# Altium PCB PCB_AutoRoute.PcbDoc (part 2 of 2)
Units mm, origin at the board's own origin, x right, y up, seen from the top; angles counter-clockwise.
Board outline 100 x 100 mm, 4 copper layers (Top Layer, AGND, PWR, Bottom Layer), stack 1.747 mm thick; 183 components, 95 nets, 503 pads, 230 vias.
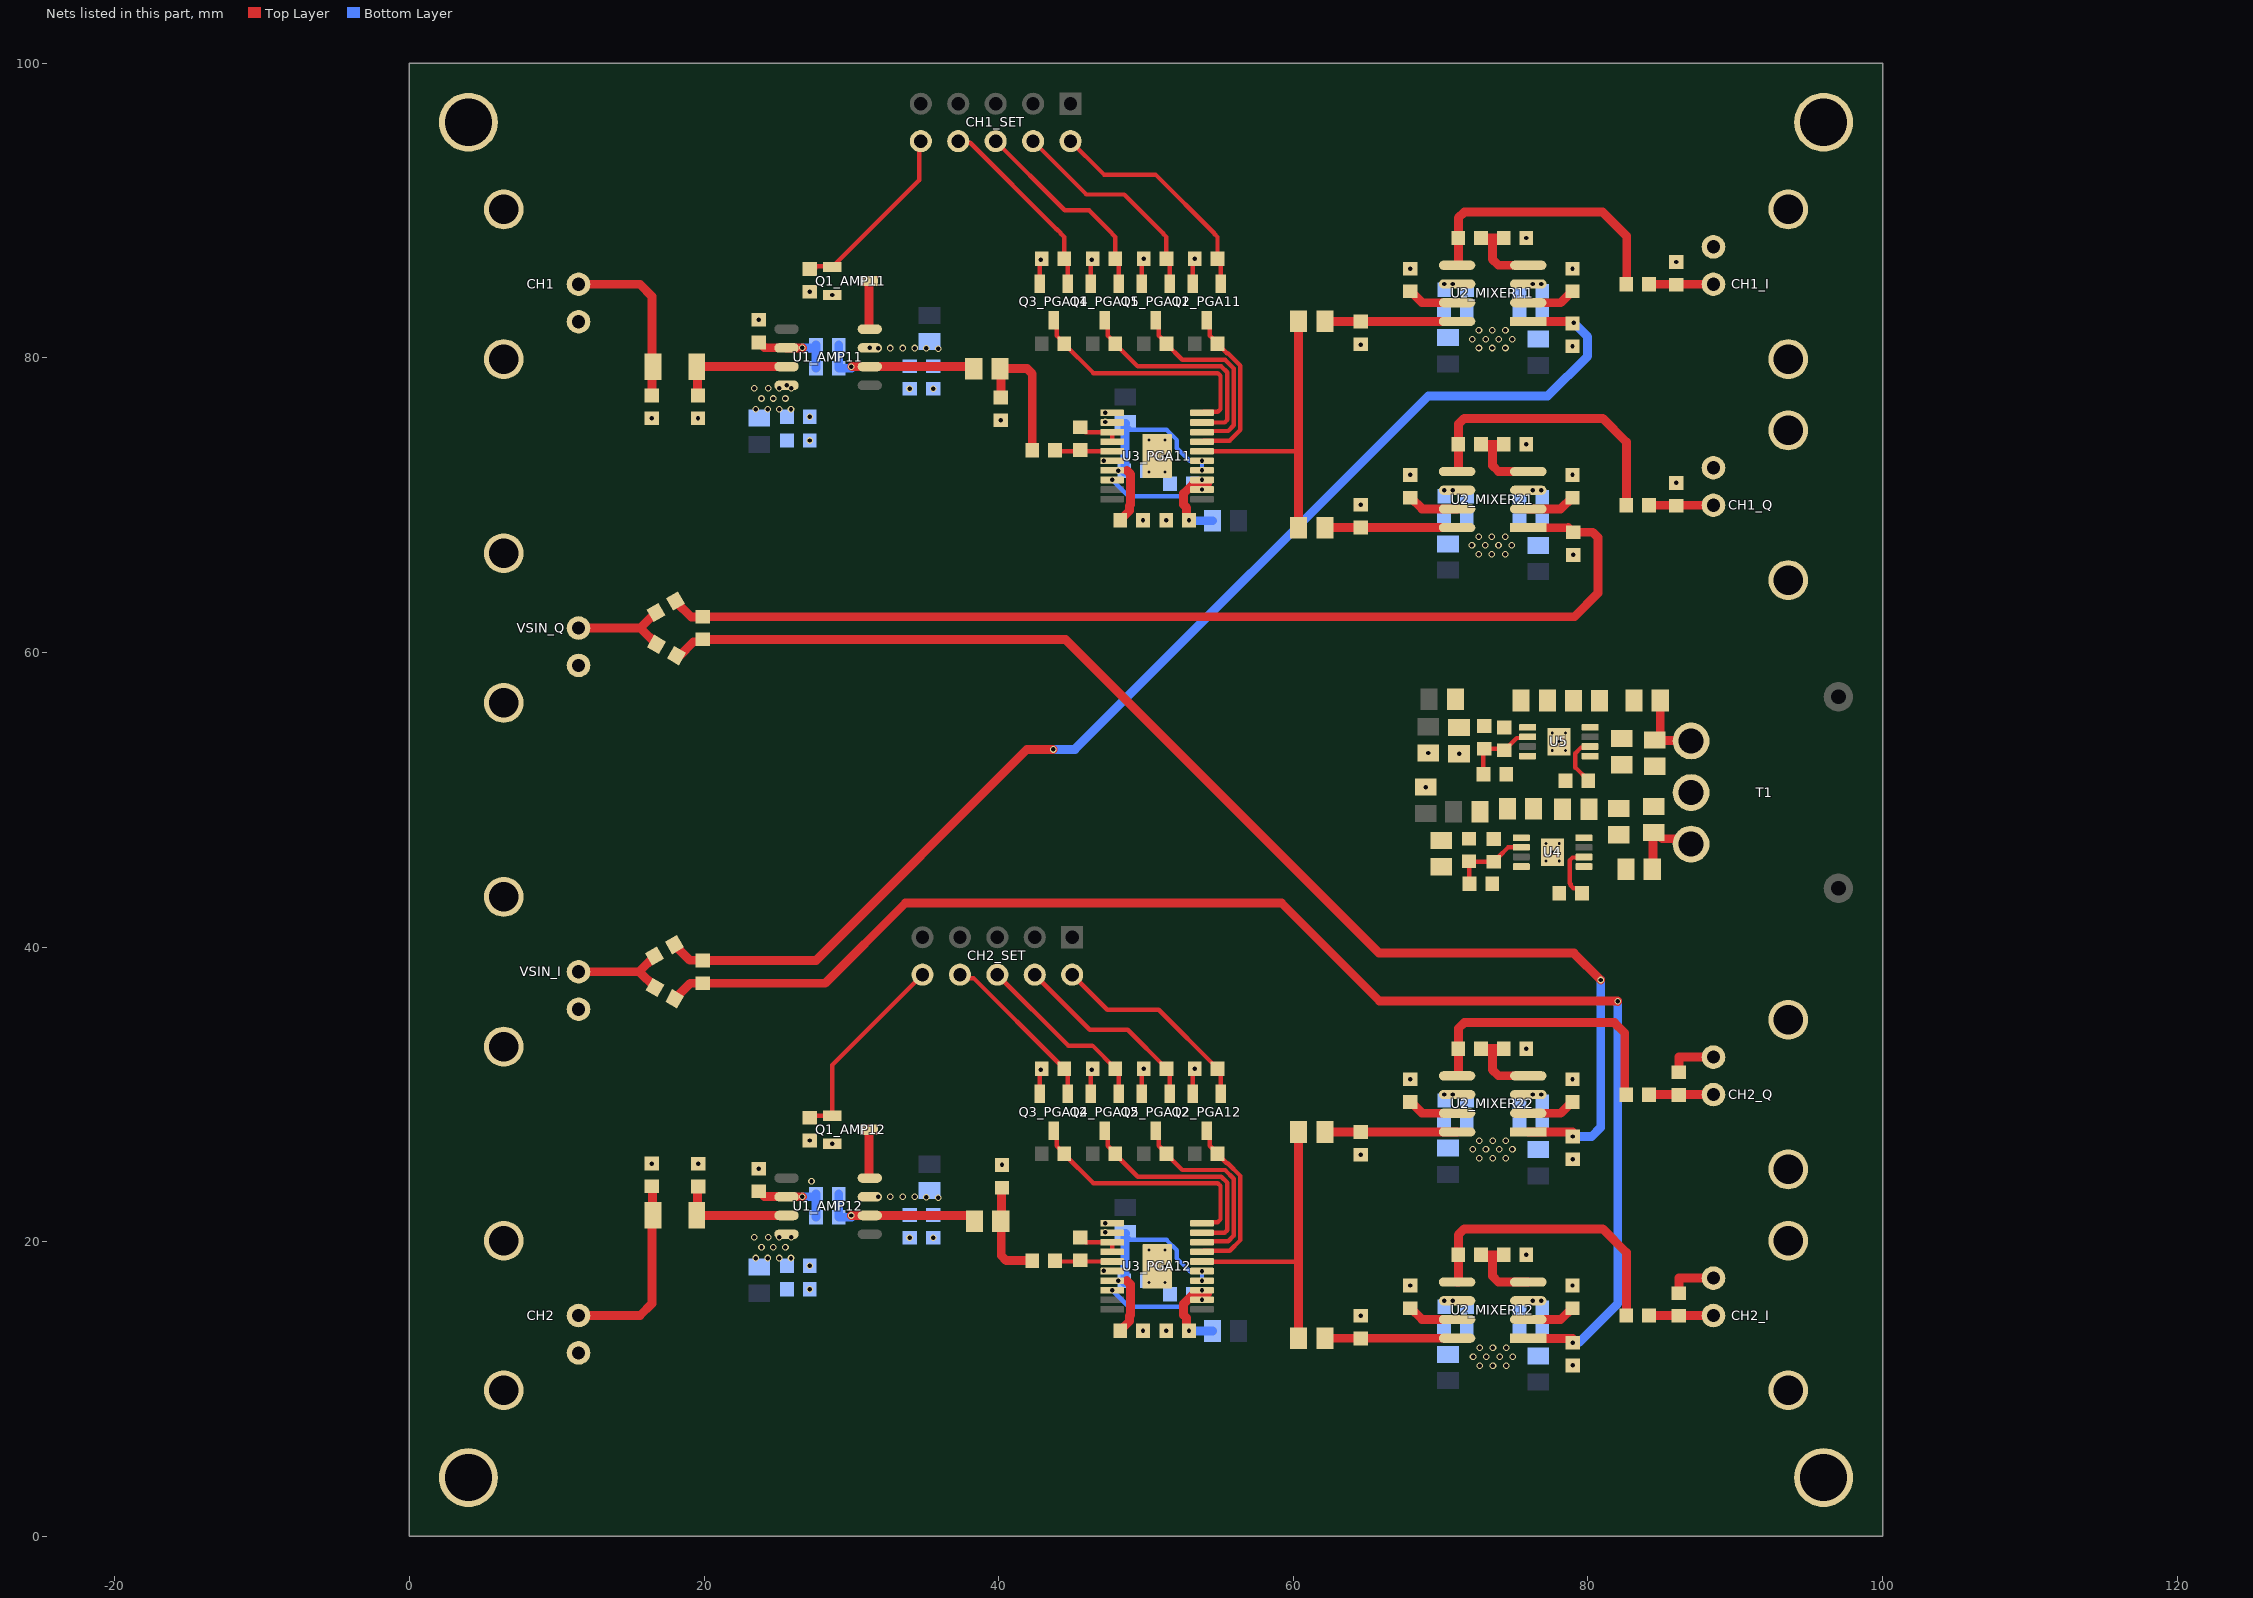
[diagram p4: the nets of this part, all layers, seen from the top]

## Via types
v1: diameter 0.45, hole 0.3, Top Layer to Bottom Layer, 208 vias
v2: diameter 0.5, hole 0.2, Top Layer to Bottom Layer, 12 vias
v3: diameter 0.5, hole 0.2, Top Layer to Bottom Layer, tented both sides, 10 vias

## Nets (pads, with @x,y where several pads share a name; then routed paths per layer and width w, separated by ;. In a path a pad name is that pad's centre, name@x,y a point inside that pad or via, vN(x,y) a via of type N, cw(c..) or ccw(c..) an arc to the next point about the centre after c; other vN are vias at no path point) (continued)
AGND: C2_CH1.1 C2_CH2.1 C3_CH1.1 C3_CH2.1 C4_AMP11.1 C4_AMP12.1 C5_AMP11.1 C5_AMP12.1 C6_AMP11.1 C6_AMP12.1 C7_AMP11.1 C7_AMP12.1 C9_MIXER11.1 C9_MIXER12.1 C9_MIXER21.1 C9_MIXER22.1 C10_MIXER11.1 C10_MIXER12.1 C10_MIXER21.1 C10_MIXER22.1 C11_MIXER11.1 C11_MIXER12.1 C11_MIXER21.1 C11_MIXER22.1 C12_MIXER11.1 C12_MIXER12.1 C12_MIXER21.1 C12_MIXER22.1 C13_PGA11.1 C13_PGA12.1 C14_PGA11.1 C14_PGA12.1 C15_PGA11.1 C15_PGA12.1 C16_PGA11.1 C16_PGA12.1 C19.1 C20.1 C21.1 C22.1 C24.1 C25.1 C26.1 C27.2 C28.2 C29.2 C30.2 C33.1 C34.1 C35.1 CH1.MH CH1_I.MH CH1_Q.MH CH2.MH CH2_I.MH CH2_Q.MH pad.MACH Q1_AMP11.2 Q1_AMP12.2 Q2_PGA11.2 Q2_PGA12.2 Q3_PGA11.2 Q3_PGA12.2 Q4_PGA11.2 Q4_PGA12.2 Q5_PGA11.2 Q5_PGA12.2 R3_AMP11.1 R3_AMP12.1 R5_AMP11.1 R5_AMP12.1 R7_MIXER11.1 R7_MIXER12.1 R7_MIXER21.1 R7_MIXER22.1 R11_PGA11.1 R11_PGA12.1 R13_PGA11.1 R13_PGA12.1 R15_PGA11.1 R15_PGA12.1 R17_PGA11.1 R17_PGA12.1 R20.1 R21.1 R23.1 R24.1 R28.1 R29.1 R30.1 R31.1 R33.1 R34.1 R41_MIXER11.1 R41_MIXER12.1 R41_MIXER21.1 R41_MIXER22.1 R42_MIXER11.1 R42_MIXER12.1 R42_MIXER21.1 R42_MIXER22.1 R43_CH1.1 R43_CH2.1 R44_CH1.1 R44_CH2.1 R45_CH1.1 R45_CH2.1 T1.2 U3_PGA11.1 U3_PGA11.2 U3_PGA11.6 U3_PGA11.21 U3_PGA12.1 U3_PGA12.2 U3_PGA12.6 U3_PGA12.21 U4.4 U4.9 U5.4 U5.9 VSIN_I.MH VSIN_Q.MH | length 20.7
  Top Layer w0.3: Q3_PGA12.2@42.782,30.048 42.782,31.611 R13_PGA12.1@42.914,31.743 ; Q3_PGA11.2@42.782,85.048 42.782,86.611 R13_PGA11.1@42.914,86.743 ; Q4_PGA12.2@46.249,30.048 46.249,31.611 R15_PGA12.1@46.381,31.743 ; Q4_PGA11.2@46.249,85.048 46.249,86.611 R15_PGA11.1@46.381,86.743 ; Q5_PGA12.2@49.715,30.048 49.715,31.611 v1(49.847,31.743) ; Q5_PGA11.2@49.715,85.048 49.715,86.611 v1(49.847,86.743) ; Q2_PGA12.2@53.182,30.048 53.182,31.611 v1(53.314,31.743) ; Q2_PGA11.2@53.182,85.048 53.182,86.611 v1(53.314,86.743)
  Top Layer w0.6: C2_CH2.1@86.175,16.515 86.175,17.54 CH2_I.MH@88.52,17.54 ; C3_CH2.1@86.175,31.515 86.175,32.54 CH2_Q.MH@88.52,32.54
  other v1: 72.65,11.6 73.55,11.6 74.45,11.6 78.975,11.61 72.2,12.2 73.1,12.2 74,12.2 74.9,12.2 72.65,12.8 73.55,12.8 74.45,12.8 49.795,13.975 51.38,13.975 64.575,14.98 27.17,16.775 67.95,17.04 78.95,17.04 47.125,18.025 27.17,18.375 75.82,19.12 33.95,20.28 35.55,20.28 47.225,20.65 47.225,21.275 27.295,24.125 23.725,24.97 40.225,25.22 19.6,25.295 16.45,25.315 78.975,25.61 72.625,25.675 73.525,25.675 74.425,25.675 64.575,25.915 72.175,26.275 73.075,26.275 73.975,26.275 74.875,26.275 28.7,26.65 72.625,26.875 73.525,26.875 74.425,26.875 27.175,26.88 67.95,31.04 78.95,31.04 42.848,31.677 46.315,31.677 75.82,33.12 69,50.865 71.25,53.135 69.15,53.185 79,66.63 72.575,66.675 73.475,66.675 74.375,66.675 72.125,67.275 73.025,67.275 73.925,67.275 74.825,67.275 72.575,67.875 73.475,67.875 74.375,67.875 49.795,68.975 51.38,68.975 64.575,70.025 86,71.515 67.95,72.06 78.95,72.06 47.125,73.025 75.82,74.14 27.17,74.397 47.225,75.65 40.15,75.78 16.46,75.905 19.59,75.905 27.17,75.997 47.225,76.275 33.95,77.902 35.55,77.902 72.6,80.675 73.5,80.675 74.4,80.675 78.95,80.8 64.575,80.9 72.15,81.275 73.05,81.275 73.95,81.275 74.85,81.275 72.6,81.875 73.5,81.875 74.4,81.875 23.725,82.592 28.7,84.272 27.175,84.502 67.95,86.06 78.95,86.06 86,86.515 42.848,86.677 46.315,86.677 75.82,88.14
  other v2: 50.202,17.243 51.302,17.243 50.202,18.343 51.302,18.343 50.202,19.443 51.302,19.443 50.202,72.243 51.302,72.243 50.202,73.343 51.302,73.343 50.202,74.443 51.302,74.443
  other v3: 77.15,45.85 78.05,45.85 77.6,46.45 77.15,47.05 78.05,47.05 77.575,53.35 78.475,53.35 78.025,53.95 77.575,54.55 78.475,54.55
AVDD_AMP11: C4_AMP11.2 C5_AMP11.2 FB1_AMP11.2 U1_AMP11.7
  other v1: 35.9,80.622 35.075,80.647 31.825,80.672 32.65,80.672 33.5,80.672 34.3,80.672 31.25,80.682
AVDD_AMP12: C4_AMP12.2 C5_AMP12.2 FB1_AMP12.2 U1_AMP12.7
  other v1: 35.9,23 35.075,23.025 31.825,23.05 32.65,23.05 33.5,23.05 34.3,23.05
AVDD_MIXER11: C9_MIXER11.2 C10_MIXER11.2 FB3_MIXER11.2 U2_MIXER11.6
  other v1: 70.243,85.02 70.818,85.02
AVDD_MIXER12: C9_MIXER12.2 C10_MIXER12.2 FB3_MIXER12.2 U2_MIXER12.6
  other v1: 70.243,16 70.818,16
AVDD_MIXER21: C9_MIXER21.2 C10_MIXER21.2 FB3_MIXER21.2 U2_MIXER21.6
  other v1: 70.243,71.02 70.818,71.02
AVDD_MIXER22: C9_MIXER22.2 C10_MIXER22.2 FB3_MIXER22.2 U2_MIXER22.6
  other v1: 70.243,30 70.818,30
AVDD_PGA11: C13_PGA11.2 C14_PGA11.2 FB5_PGA11.2 U3_PGA11.8 U3_PGA11.12 U3_PGA11.13 | length 12.2
  Top Layer w0.6: v1(52.92,68.975) 52.755,69.14 52.755,69.829 52.55,70.035 52.55,70.801 53.223,71.475 54.175,71.475
  Bottom Layer w0.3: v1(47.702,71.718) 48.82,70.6 52.55,70.6 53.018,71.068 v1(53.802,71.068)
  Bottom Layer w0.6: v1(52.92,68.975) 52.945,68.95 FB5_PGA11.2@54.51,68.95
  other v1: 53.802,71.718
AVDD_PGA12: C13_PGA12.2 C14_PGA12.2 FB5_PGA12.2 U3_PGA12.8 U3_PGA12.12 U3_PGA12.13 | length 12.2
  Top Layer w0.6: v1(52.92,13.975) 52.755,14.14 52.755,14.829 52.55,15.035 52.55,15.801 53.223,16.475 54.175,16.475
  Bottom Layer w0.3: v1(47.702,16.718) 48.82,15.6 52.55,15.6 53.018,16.068 v1(53.802,16.068)
  Bottom Layer w0.6: v1(52.92,13.975) 52.945,13.95 FB5_PGA12.2@54.51,13.95
  other v1: 53.802,16.718
AVEE_AMP11: C6_AMP11.2 C7_AMP11.2 FB2_AMP11.2 U1_AMP11.4
  other v1: 23.5,76.522 24.325,76.522 25.1,76.522 25.9,76.522 23.9,77.247 24.7,77.247 25.525,77.247 23.4,77.947 24.35,77.947 25.1,77.947 25.925,77.947 25.6,78.142
AVEE_AMP12: C6_AMP12.2 C7_AMP12.2 FB2_AMP12.2 U1_AMP12.4
  other v1: 23.5,18.9 24.325,18.9 25.1,18.9 25.9,18.9 23.9,19.625 24.7,19.625 25.525,19.625 23.4,20.325 24.35,20.325 25.1,20.325 25.925,20.325
AVEE_MIXER11: C11_MIXER11.2 C12_MIXER11.2 FB4_MIXER11.2 U2_MIXER11.3
  other v1: 76.25,85.02 76.825,85.02
AVEE_MIXER12: C11_MIXER12.2 C12_MIXER12.2 FB4_MIXER12.2 U2_MIXER12.3
  other v1: 76.25,16 76.825,16
AVEE_MIXER21: C11_MIXER21.2 C12_MIXER21.2 FB4_MIXER21.2 U2_MIXER21.3
  other v1: 76.25,71.02 76.825,71.02
AVEE_MIXER22: C11_MIXER22.2 C12_MIXER22.2 FB4_MIXER22.2 U2_MIXER22.3
  other v1: 76.25,30 76.825,30
AVEE_PGA11: C15_PGA11.2 C16_PGA11.2 FB6_PGA11.2 U3_PGA11.7 U3_PGA11.14 U3_PGA11.15 | length 14.4
  Top Layer w0.6: C15_PGA11.2@48.255,68.975 48.255,69 48.878,69.623 48.878,69.958 48.954,70.035 48.954,72.101 48.688,72.368
  Bottom Layer w0.3: FB6_PGA11.2@48.565,75.525 48.96,75.13 51.396,75.13 52.1,74.426 52.1,73.875 52.957,73.018 v1(53.802,73.018) v1(53.802,72.368)
  Bottom Layer w0.6: C16_PGA11.2@48.53,72.25 48.565,72.285 48.565,75.525 FB6_PGA11.2@48.6,75.56
  other v1: 48.125,72.35
AVEE_PGA12: C15_PGA12.2 C16_PGA12.2 FB6_PGA12.2 U3_PGA12.7 U3_PGA12.14 U3_PGA12.15 | length 14.4
  Top Layer w0.6: C15_PGA12.2@48.255,13.975 48.255,14 48.878,14.623 48.878,14.958 48.954,15.035 48.954,17.101 48.688,17.368
  Bottom Layer w0.3: FB6_PGA12.2@48.565,20.525 48.96,20.13 51.396,20.13 52.1,19.426 52.1,18.875 52.957,18.018 v1(53.802,18.018) v1(53.802,17.368)
  Bottom Layer w0.6: C16_PGA12.2@48.53,17.25 48.565,17.285 48.565,20.525 FB6_PGA12.2@48.6,20.56
  other v1: 48.125,17.35
CH1_CONT_BIT0: CH1_SET.10 Q1_AMP11.1 R5_AMP11.2 | length 12.9
  Top Layer w0.3: R5_AMP11.2@27.562,86.042 27.351,86.042 27.175,86.217 Q1_AMP11.1@28.472,86.217 ; Q1_AMP11.1@28.7,86.172 34.602,92.074 CH1_SET.10@34.602,94.83
CH1_CONT_BIT1: CH1_SET.2 Q2_PGA11.1 R11_PGA11.2 | length 16.1
  Top Layer w0.3: CH1_SET.2@44.762,94.83 47.147,92.445 50.644,92.445 54.626,88.463 54.626,88.438 54.854,88.21 R11_PGA11.2@54.854,86.743 55.082,86.515 Q2_PGA11.1@55.082,85.048
CH1_CONT_BIT2: CH1_SET.8 Q3_PGA11.1 R13_PGA11.2 | length 13.3
  Top Layer w0.3: CH1_SET.8@37.142,94.83 37.372,94.6 38.064,94.6 43.886,88.778 43.911,88.778 44.226,88.463 44.226,88.438 44.454,88.21 R13_PGA11.2@44.454,86.743 44.682,86.515 Q3_PGA11.1@44.682,85.048
CH1_CONT_BIT3: CH1_SET.6 Q4_PGA11.1 R15_PGA11.2 | length 14.3
  Top Layer w0.3: CH1_SET.6@39.682,94.83 44.492,90.02 46.136,90.02 47.693,88.463 47.693,88.438 47.921,88.21 R15_PGA11.2@47.921,86.743 48.149,86.515 Q4_PGA11.1@48.149,85.048
CH1_CONT_BIT4: CH1_SET.4 Q5_PGA11.1 R17_PGA11.2 | length 15.2
  Top Layer w0.3: CH1_SET.4@42.222,94.83 45.957,91.095 48.527,91.095 51.159,88.463 51.159,88.438 51.387,88.21 R17_PGA11.2@51.387,86.743 51.615,86.515 Q5_PGA11.1@51.615,85.048
CH2_CONT_BIT0: CH2_SET.10 Q1_AMP12.1 R5_AMP12.2 | length 13.7
  Top Layer w0.3: R5_AMP12.2@27.175,28.42 27.305,28.55 Q1_AMP12.1@28.7,28.55 28.7,32.005 CH2_SET.10@34.83,38.135
CH2_CONT_BIT1: CH2_SET.2 Q2_PGA12.1 R11_PGA12.2 | length 14.3
  Top Layer w0.3: CH2_SET.2@44.99,38.135 47.375,35.75 50.872,35.75 R11_PGA12.2@54.854,31.768 ; R11_PGA12.2@54.854,31.743 55.082,31.515 Q2_PGA12.1@55.082,30.048
CH2_CONT_BIT2: CH2_SET.8 Q3_PGA12.1 R13_PGA12.2 | length 11
  Top Layer w0.3: CH2_SET.8@37.37,38.135 37.6,37.905 38.292,37.905 R13_PGA12.2@44.114,32.083 ; R13_PGA12.2@44.454,31.743 44.682,31.515 Q3_PGA12.1@44.682,30.048
CH2_CONT_BIT3: CH2_SET.6 Q4_PGA12.1 R15_PGA12.2 | length 12.4
  Top Layer w0.3: CH2_SET.6@39.91,38.135 44.72,33.325 46.364,33.325 R15_PGA12.2@47.921,31.768 ; R15_PGA12.2@47.921,31.743 48.149,31.515 Q4_PGA12.1@48.149,30.048
CH2_CONT_BIT4: CH2_SET.4 Q5_PGA12.1 R17_PGA12.2 | length 13.4
  Top Layer w0.3: CH2_SET.4@42.45,38.135 46.185,34.4 48.755,34.4 R17_PGA12.2@51.387,31.768 ; R17_PGA12.2@51.387,31.743 51.615,31.515 Q5_PGA12.1@51.615,30.048
NetC1_CH1_1: C1_CH1.1 C8_AMP11.2 R4_AMP11.2 U1_AMP11.6 | length 11
  Top Layer w0.6: v1@30.025,79.412 U1_AMP11.6@31.25,79.412 38.31,79.412 C1_CH1.1@38.31,79.275
  Bottom Layer w0.6: C8_AMP11.2@29.145,80.872 R4_AMP11.2@29.145,79.297 30.025,79.297 v1@30.025,79.412
  other v1: 30,79.412
NetC1_CH1_2: C1_CH1.2 R8_PGA11.1 R43_CH1.2 | length 9.6
  Top Layer w0.6: R43_CH1.2@40.15,77.32 40.15,79.275 C1_CH1.2@40.09,79.275 41.931,79.275 42.282,78.924 R8_PGA11.1@42.282,73.723
NetC1_CH2_1: C1_CH2.1 C8_AMP12.2 R4_AMP12.2 U1_AMP12.6 | length 11.2
  Top Layer w0.6: v1(30,21.79) 38.08,21.79 38.36,21.51 C1_CH2.1@38.36,21.4
  Bottom Layer w0.6: C8_AMP12.2@29.145,23.25 R4_AMP12.2@29.145,21.675 30.025,21.675 v1@30.025,21.79
NetC1_CH2_2: C1_CH2.2 R8_PGA12.1 R43_CH2.2 | length 7.2
  Top Layer w0.6: C1_CH2.2@40.14,21.4 C1_CH2.2@40.175,21.435 ; R43_CH2.2@40.225,23.68 40.183,23.637 C1_CH2.2@40.183,21.75 ; R8_PGA12.1@42.282,18.723 40.526,18.723 40.175,19.074 C1_CH2.2@40.175,21.435 ; C1_CH2.2@40.175,21.435 40.175,21.742 C1_CH2.2@40.183,21.75 ; C1_CH2.2@40.175,21.435 40.183,21.442 C1_CH2.2@40.183,21.75
NetC2_CH1_2: C2_CH1.2 CH1_I.1 R1_CH1.1 | length 4.3
  Top Layer w0.6: R1_CH1.1@84.17,85 CH1_I.1@88.52,85
NetC2_CH2_2: C2_CH2.2 CH2_I.1 R1_CH2.1 | length 4.4
  Top Layer w0.6: R1_CH2.1@84.145,15 CH2_I.1@88.52,15
NetC3_CH1_2: C3_CH1.2 CH1_Q.1 R2_CH1.1 | length 4.3
  Top Layer w0.6: R2_CH1.1@84.17,70 CH1_Q.1@88.52,70
NetC3_CH2_2: C3_CH2.2 CH2_Q.1 R2_CH2.1 | length 4.4
  Top Layer w0.6: R2_CH2.1@84.145,30 CH2_Q.1@88.52,30
NetC8_AMP11_1: C8_AMP11.1 R3_AMP11.2 R4_AMP11.1 U1_AMP11.2 | length 5.7
  Top Layer w0.6: R3_AMP11.2@23.725,81.052 23.75,81.052 24.11,80.691 25.59,80.691 U1_AMP11.2@25.6,80.682 v1(26.675,80.682)
  Bottom Layer w0.6: v1(26.675,80.682) 27.44,80.682 C8_AMP11.1@27.605,80.847 ; R4_AMP11.1@27.605,79.297 C8_AMP11.1@27.605,80.847 ; C8_AMP11.1@27.605,80.872 C8_AMP11.1@27.605,80.847
NetC8_AMP12_1: C8_AMP12.1 R3_AMP12.2 R4_AMP12.1 U1_AMP12.2 | length 5.7
  Top Layer w0.6: R3_AMP12.2@23.725,23.43 23.75,23.43 24.11,23.07 25.59,23.07 U1_AMP12.2@25.6,23.06 v1(26.675,23.06)
  Bottom Layer w0.6: v1(26.675,23.06) 27.44,23.06 C8_AMP12.1@27.605,23.225 ; R4_AMP12.1@27.605,21.675 C8_AMP12.1@27.605,23.225 ; C8_AMP12.1@27.605,23.25 C8_AMP12.1@27.605,23.225
NetC17_1: C17.1 CH1.1 R20.2 | length 12.1
  Top Layer w0.6: CH1.1@11.48,85 15.65,85 16.46,84.19 R20.2@16.46,77.445
NetC17_2: C17.2 R21.2 U1_AMP11.3 | length 8.1
  Top Layer w0.6: R21.2@19.59,77.445 19.552,77.483 19.552,79.374 C17.2@19.515,79.412 U1_AMP11.3@25.6,79.412
NetC18_1: C18.1 CH2.1 R30.2 | length 14.1
  Top Layer w0.6: CH2.1@11.48,15 15.65,15 16.46,15.81 C18.1@16.46,22.555 ; R30.2@16.45,23.775 16.492,23.733 16.492,21.833 C18.1@16.535,21.79
NetC18_2: C18.2 R31.2 U1_AMP12.3 | length 8.1
  Top Layer w0.6: R31.2@19.6,23.755 19.557,23.712 19.557,21.833 C18.2@19.515,21.79 U1_AMP12.3@25.6,21.79
NetC19_2: C19.2 FB7.2 T1.1 | length 5.4
  Top Layer w0.6: FB7.2@84.365,45.3 84.42,45.355 84.42,47.73 C19.2@84.475,47.785 84.63,47.785 85.051,47.364 86.636,47.364 T1.1@87,47
NetC21_2: C21.2 C23.2 C25.2 FB8.2 R32.2 U4.1
NetC23_1: C23.1 R32.1 R33.2 U4.2 | length 5.5
  Top Layer w0.3: C23.1@71.925,45.83 C23.1@71.95,45.805 ; R33.2@71.955,44.3 71.955,45.8 C23.1@71.95,45.805 ; U4.2@75.475,46.775 74.57,46.775 73.94,46.145 73.94,46.12 73.625,45.805 C23.1@71.95,45.805
NetC26_2: C26.2 U4.6 | length 3.8
  Top Layer w0.3: C26.2@79.595,43.675 79.595,43.7 79.28,44.015 78.998,44.015 78.822,44.191 78.822,44.29 78.775,44.338 78.775,45.916 78.951,46.092 79.692,46.092 U4.6@79.725,46.125
NetC27_1: C27.1 FB9.1 T1.3 | length 5.3
  Top Layer w0.6: C27.1@84.525,54.065 84.557,54.033 C27.1@84.592,54.033 ; FB9.1@84.905,56.75 84.905,54.345 C27.1@84.592,54.033 ; T1.3@87,54 86.967,54.033 C27.1@84.592,54.033
NetC28_1: C28.1 C34.2 FB9.2 U5.5 U5.8
NetC29_1: C29.1 C35.2 C36.2 FB10.2 R35.2 U5.1
NetC31_CH1_1: C31_CH1.1 C32_CH1.1 U3_PGA11.16 | length 20.5
  Top Layer w0.3: U3_PGA11.16@53.802,73.668 60.253,73.668
  Top Layer w0.6: C32_CH1.1@60.36,68.48 60.36,73.775 C31_CH1.1@60.36,82.48
NetC31_CH1_2: C31_CH1.2 R44_CH1.2 U2_MIXER11.8 | length 9
  Top Layer w0.6: C31_CH1.2@62.14,82.48 U2_MIXER11.8@71.118,82.48
NetC31_CH2_1: C31_CH2.1 C32_CH2.1 U3_PGA12.16 | length 20.5
  Top Layer w0.3: U3_PGA12.16@53.802,18.648 60.253,18.648
  Top Layer w0.6: C31_CH2.1@60.36,13.46 60.36,18.755 C32_CH2.1@60.36,27.46
NetC31_CH2_2: C31_CH2.2 R44_CH2.2 U2_MIXER12.8 | length 9
  Top Layer w0.6: C31_CH2.2@62.14,13.46 U2_MIXER12.8@71.118,13.46
NetC32_CH1_2: C32_CH1.2 R45_CH1.2 U2_MIXER21.8 | length 9
  Top Layer w0.6: C32_CH1.2@62.14,68.48 U2_MIXER21.8@71.118,68.48
NetC32_CH2_2: C32_CH2.2 R45_CH2.2 U2_MIXER22.8 | length 9
  Top Layer w0.6: C32_CH2.2@62.14,27.46 U2_MIXER22.8@71.118,27.46
NetC33_2: C33.2 U5.6 | length 3.4
  Top Layer w0.3: C33.2@80.02,51.3 80.02,51.325 79.15,52.195 79.15,53.174 79.526,53.55 80.075,53.55 U5.6@80.15,53.625
NetC36_1: C36.1 R34.2 R35.1 U5.2 | length 5.1
  Top Layer w0.3: R34.2@72.905,51.75 72.905,53.41 C36.1@72.975,53.48 74.25,53.48 R35.1@74.35,53.38 ; R35.1@74.325,53.38 R35.1@74.35,53.38 ; U5.2@75.9,54.275 75.825,54.2 75.17,54.2 R35.1@74.35,53.38
NetQ1_AMP11_3: Q1_AMP11.3 U1_AMP11.8 | length 3.3
  Top Layer w0.6: Q1_AMP11.3@31.2,85.222 31.2,81.975 31.223,81.952 U1_AMP11.8@31.25,81.952
NetQ1_AMP12_3: Q1_AMP12.3 U1_AMP12.8 | length 3.3
  Top Layer w0.6: Q1_AMP12.3@31.2,27.6 31.2,24.353 31.223,24.33 U1_AMP12.8@31.25,24.33
NetQ2_PGA11_3: Q2_PGA11.3 R10_PGA11.1 U3_PGA11.17 | length 11.4
  Top Layer w0.3: U3_PGA11.17@53.802,74.318 53.877,74.393 55.677,74.393 56.412,75.128 56.412,79.472 55.556,80.328 55.474,80.328 54.854,80.948 54.854,80.998 54.332,81.52 54.332,82.348 Q2_PGA11.3@54.132,82.548
NetQ2_PGA12_3: Q2_PGA12.3 R10_PGA12.1 U3_PGA12.17 | length 11.4
  Top Layer w0.3: U3_PGA12.17@53.802,19.318 53.877,19.393 55.677,19.393 56.412,20.128 56.412,24.472 55.556,25.328 55.474,25.328 54.854,25.948 54.854,25.998 54.332,26.52 54.332,27.348 Q2_PGA12.3@54.132,27.548
NetQ3_PGA11_3: Q3_PGA11.3 R12_PGA11.1 U3_PGA11.20 | length 17
  Top Layer w0.3: Q3_PGA11.3@43.732,82.548 43.932,82.348 43.932,81.52 44.454,80.998 R12_PGA11.1@44.454,80.973 44.454,80.948 46.431,78.971 54.879,78.971 55.055,78.795 55.055,76.523 54.875,76.343 53.877,76.343 U3_PGA11.20@53.802,76.268
NetQ3_PGA12_3: Q3_PGA12.3 R12_PGA12.1 U3_PGA12.20 | length 17
  Top Layer w0.3: Q3_PGA12.3@43.732,27.548 43.932,27.348 43.932,26.52 44.454,25.998 R12_PGA12.1@44.454,25.973 44.454,25.948 46.431,23.971 54.879,23.971 55.055,23.795 55.055,21.523 54.875,21.343 53.877,21.343 U3_PGA12.20@53.802,21.268
NetQ4_PGA11_3: Q4_PGA11.3 R14_PGA11.1 U3_PGA11.19 | length 15.3
  Top Layer w0.3: Q4_PGA11.3@47.199,82.548 47.399,82.348 47.399,81.52 47.921,80.998 R14_PGA11.1@47.921,80.973 ; R14_PGA11.1@47.921,80.948 49.446,79.423 55.107,79.423 55.507,79.023 55.507,75.794 55.331,75.618 U3_PGA11.19@53.802,75.618
NetQ4_PGA12_3: Q4_PGA12.3 R14_PGA12.1 U3_PGA12.19 | length 15.3
  Top Layer w0.3: Q4_PGA12.3@47.199,27.548 47.399,27.348 47.399,26.52 47.921,25.998 R14_PGA12.1@47.921,25.973 ; R14_PGA12.1@47.921,25.948 49.446,24.423 55.107,24.423 55.507,24.023 55.507,20.794 55.331,20.618 U3_PGA12.19@53.802,20.618
NetQ5_PGA11_3: Q5_PGA11.3 R16_PGA11.1 U3_PGA11.18 | length 13.4
  Top Layer w0.3: Q5_PGA11.3@50.665,82.548 50.865,82.348 50.865,81.52 51.387,80.998 51.387,80.948 52.46,79.875 55.369,79.875 55.959,79.285 55.959,75.425 55.577,75.043 53.877,75.043 U3_PGA11.18@53.802,74.968
NetQ5_PGA12_3: Q5_PGA12.3 R16_PGA12.1 U3_PGA12.18 | length 13.4
  Top Layer w0.3: Q5_PGA12.3@50.665,27.548 50.865,27.348 50.865,26.52 51.387,25.998 51.387,25.948 52.46,24.875 55.369,24.875 55.959,24.285 55.959,20.425 55.577,20.043 53.877,20.043 U3_PGA12.18@53.802,19.968
NetR1_CH1_2: R1_CH1.2 R6_MIXER11.2 U2_MIXER11.5 | length 18.8
  Top Layer w0.6: U2_MIXER11.5@71.118,86.29 71.195,86.29 71.205,86.3 R6_MIXER11.2@71.205,88.14 71.205,89.505 71.6,89.9 81,89.9 82.63,88.27 R1_CH1.2@82.63,85
NetR1_CH2_2: R1_CH2.2 R6_MIXER12.2 U2_MIXER12.5 | length 19.8
  Top Layer w0.6: U2_MIXER12.5@71.118,17.27 71.195,17.27 71.205,17.28 R6_MIXER12.2@71.205,19.12 71.205,20.485 71.6,20.88 81,20.88 82.605,19.275 R1_CH2.2@82.605,15
NetR2_CH1_2: R2_CH1.2 R6_MIXER21.2 U2_MIXER21.5 | length 19.8
  Top Layer w0.6: U2_MIXER21.5@71.118,72.29 71.195,72.29 71.205,72.3 R6_MIXER21.2@71.205,74.14 71.205,75.505 71.6,75.9 81,75.9 82.605,74.295 R2_CH1.2@82.605,70
NetR2_CH2_2: R2_CH2.2 R6_MIXER22.2 U2_MIXER22.5 | length 19.3
  Top Layer w0.6: U2_MIXER22.5@71.118,31.27 71.195,31.27 71.205,31.28 R6_MIXER22.2@71.205,33.12 71.205,34.485 71.6,34.88 81.795,34.88 82.5,34.175 82.5,30.105 R2_CH2.2@82.605,30
NetR8_PGA11_2: R8_PGA11.2 R9_PGA11.1 U3_PGA11.5 | length 3.9
  Top Layer w0.3: R8_PGA11.2@43.822,73.723 43.877,73.668 U3_PGA11.5@47.702,73.668
NetR8_PGA12_2: R8_PGA12.2 R9_PGA12.1 U3_PGA12.5 | length 3.9
  Top Layer w0.3: R8_PGA12.2@43.822,18.723 43.877,18.668 U3_PGA12.5@47.702,18.668
NetR18_2: R18.2 R22.2 VSIN_Q.1 | length 7.3
  Top Layer w0.6: VSIN_Q.1@11.48,61.667 15.677,61.667 ; R18.2@16.741,62.73 15.678,61.667 15.677,61.667 ; R22.2@16.783,60.56 15.677,61.667
NetR25_2: R25.2 R27.2 VSIN_I.1 | length 7.1
  Top Layer w0.6: VSIN_I.1@11.48,38.333 15.583,38.333 ; R25.2@16.65,39.4 15.583,38.333 ; R27.2@16.675,37.27 15.612,38.333 15.583,38.333
NetR41_MIXER11_2: R41_MIXER11.2 U2_MIXER11.7 | length 3.5
  Top Layer w0.6: R41_MIXER11.2@67.95,84.52 67.975,84.52 68.745,83.75 U2_MIXER11.7@71.118,83.75
NetR41_MIXER12_2: R41_MIXER12.2 U2_MIXER12.7 | length 3.5
  Top Layer w0.6: R41_MIXER12.2@67.95,15.5 67.975,15.5 68.745,14.73 U2_MIXER12.7@71.118,14.73
NetR41_MIXER21_2: R41_MIXER21.2 U2_MIXER21.7 | length 3.5
  Top Layer w0.6: R41_MIXER21.2@67.95,70.52 67.975,70.52 68.745,69.75 U2_MIXER21.7@71.118,69.75
NetR41_MIXER22_2: R41_MIXER22.2 U2_MIXER22.7 | length 3.5
  Top Layer w0.6: R41_MIXER22.2@67.95,29.5 67.975,29.5 68.745,28.73 U2_MIXER22.7@71.118,28.73
NetR42_MIXER11_2: R42_MIXER11.2 U2_MIXER11.2 | length 3.3
  Top Layer w0.6: U2_MIXER11.2@75.95,83.75 78.155,83.75 78.925,84.52 R42_MIXER11.2@78.95,84.52
NetR42_MIXER12_2: R42_MIXER12.2 U2_MIXER12.2 | length 3.3
  Top Layer w0.6: U2_MIXER12.2@75.95,14.73 78.155,14.73 78.925,15.5 R42_MIXER12.2@78.95,15.5
NetR42_MIXER21_2: R42_MIXER21.2 U2_MIXER21.2 | length 3.3
  Top Layer w0.6: U2_MIXER21.2@75.95,69.75 78.155,69.75 78.925,70.52 R42_MIXER21.2@78.95,70.52
NetR42_MIXER22_2: R42_MIXER22.2 U2_MIXER22.2 | length 3.3
  Top Layer w0.6: U2_MIXER22.2@75.95,28.73 78.155,28.73 78.925,29.5 R42_MIXER22.2@78.95,29.5
VDD_13P0V: C20.2 C24.2 FB7.1 U4.5 U4.8
VINPGA-_PGA11: R9_PGA11.2 U3_PGA11.3 U3_PGA11.4 | length 3
  Top Layer w0.3: R9_PGA11.2@45.527,75.293 45.552,75.293 45.877,74.968 U3_PGA11.3@47.702,74.968 U3_PGA11.4@47.702,74.318
VINPGA-_PGA12: R9_PGA12.2 U3_PGA12.3 U3_PGA12.4 | length 3
  Top Layer w0.3: R9_PGA12.2@45.527,20.293 45.552,20.293 45.877,19.968 U3_PGA12.3@47.702,19.968 U3_PGA12.4@47.702,19.318
VSIN_I_CH1: R24.2 R25.1 R26.1 U2_MIXER11.1 | length 85.2
  Top Layer w0.6: R25.1@17.984,40.17 19.04,39.114 19.915,39.114 R26.1@19.925,39.103 27.603,39.103 41.925,53.425 v1(43.7,53.425) ; U2_MIXER11.1@75.95,82.48 75.961,82.469 78.946,82.469 v1(79.025,82.39)
  Bottom Layer w0.6: v1(43.7,53.425) 45.175,53.425 69.175,77.425 77.275,77.425 79.975,80.125 79.975,81.44 v1(79.025,82.39)
VSIN_I_CH2: R26.2 R27.1 R28.2 U2_MIXER12.1 | length 97.7
  Top Layer w0.6: R27.1@18.009,36.5 19.065,37.556 R26.2@19.918,37.556 ; R26.2@19.925,37.563 R26.2@19.918,37.556 ; U2_MIXER12.1@75.95,13.46 75.961,13.449 R28.2@78.676,13.449 ; R28.2@78.665,13.46 R28.2@78.676,13.449 ; v1(78.975,13.15) R28.2@78.676,13.449 ; R28.2@79.025,13.37 78.946,13.449 R28.2@78.676,13.449 ; v1(82.025,36.325) 82,36.35 65.85,36.35 59.2,43 33.675,43 28.231,37.556 R26.2@19.918,37.556
  Bottom Layer w0.6: v1(78.975,13.15) 79.375,13.15 82.025,15.8 v1(82.025,36.325)
VSIN_Q_CH1: R18.1 R19.1 R23.2 U2_MIXER21.1 | length 72.6
  Top Layer w0.6: R18.1@18.092,63.46 19.148,62.404 20.023,62.404 R19.1@20.033,62.393 ; R19.1@19.925,62.437 79.087,62.437 80.675,64.025 80.675,67.819 80.324,68.17 R23.2@79,68.17 ; U2_MIXER21.1@75.95,68.48 75.961,68.469 R23.2@78.676,68.469 ; R23.2@78.665,68.48 R23.2@78.676,68.469 ; R23.2@78.975,68.17 R23.2@78.676,68.469
VSIN_Q_CH2: R19.2 R22.1 R29.2 U2_MIXER22.1 | length 88.5
  Top Layer w0.6: R22.1@18.117,59.79 18.346,59.79 19.288,60.732 19.76,60.732 R19.2@19.925,60.897 44.528,60.897 65.825,39.6 79.043,39.6 v1(80.869,37.774) ; U2_MIXER22.1@75.95,27.46 75.961,27.449 R29.2@78.676,27.449 ; R29.2@78.665,27.46 R29.2@78.676,27.449 ; v1(78.975,27.15) R29.2@78.676,27.449 ; R29.2@79.025,27.37 78.946,27.449 R29.2@78.676,27.449
  Bottom Layer w0.6: v1(78.975,27.15) 80.25,27.15 80.869,27.769 v1(80.869,37.774)
Z_MIXER11: R6_MIXER11.1 R7_MIXER11.2 U2_MIXER11.4 | length 5.6
  Top Layer w0.6: R6_MIXER11.1@72.745,88.14 73.512,88.14 ; R7_MIXER11.2@74.28,88.14 73.512,88.14 ; U2_MIXER11.4@75.95,86.29 73.93,86.29 73.512,86.708 73.512,88.14
Z_MIXER12: R6_MIXER12.1 R7_MIXER12.2 U2_MIXER12.4 | length 5.6
  Top Layer w0.6: R6_MIXER12.1@72.745,19.12 73.512,19.12 ; R7_MIXER12.2@74.28,19.12 73.512,19.12 ; U2_MIXER12.4@75.95,17.27 73.93,17.27 73.512,17.687 73.512,19.12
Z_MIXER21: R6_MIXER21.1 R7_MIXER21.2 U2_MIXER21.4 | length 5.6
  Top Layer w0.6: R6_MIXER21.1@72.745,74.14 73.512,74.14 ; R7_MIXER21.2@74.28,74.14 73.512,74.14 ; U2_MIXER21.4@75.95,72.29 73.93,72.29 73.512,72.708 73.512,74.14
Z_MIXER22: R6_MIXER22.1 R7_MIXER22.2 U2_MIXER22.4 | length 5.6
  Top Layer w0.6: R6_MIXER22.1@72.745,33.12 73.512,33.12 ; R7_MIXER22.2@74.28,33.12 73.512,33.12 ; U2_MIXER22.4@75.95,31.27 73.93,31.27 73.512,31.687 73.512,33.12
pads on no net: T1.MACH U1_AMP11.1 U1_AMP11.5 U1_AMP12.1 U1_AMP12.5 U3_PGA11.9 U3_PGA11.10 U3_PGA11.11 U3_PGA12.9 U3_PGA12.10 U3_PGA12.11 U4.3 U4.7 U5.3 U5.7

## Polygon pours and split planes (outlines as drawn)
AGND on Bottom Layer "AGND_L04_P029" (solid, pour order 29): 49.625,19.825 49.625,15.925 52.125,15.925 52.125,19.825 49.6,19.825
AGND on Bottom Layer "AGND_L04_P028" (solid, pour order 28): 49.625,74.825 49.625,70.925 52.125,70.925 52.125,74.825 49.6,74.825
AVDD_MIXER11 on Bottom Layer "AVDD_MIXER11_L04_P021" (solid, pour order 21): 71.145,85.395 71.145,82.37 71.42,82.095 71.42,80.545 69.545,80.545 69.545,85.395
AVDD_MIXER21 on Bottom Layer "AVDD_MIXER21_L04_P018" (solid, pour order 18): 71.145,71.395 71.145,68.37 71.42,68.095 71.42,66.545 69.545,66.545 69.545,71.395
AVDD_MIXER22 on Bottom Layer "AVDD_MIXER22_L04_P015" (solid, pour order 15): 71.145,30.375 71.145,27.35 71.42,27.075 71.42,25.525 69.545,25.525 69.545,30.375
AVEE_AMP11 on Bottom Layer "AVEE_AMP11_L04_P024" (solid, pour order 24): 26.55,78.55 26.55,73.25 22.7,73.25 22.7,78.55
AVDD_AMP11 on Bottom Layer "AVDD_AMP11_L04_P023" (solid, pour order 23): 36.325,81.975 32.575,81.975 32.575,81.275 30.275,81.275 30.275,80.275 33.125,80.275 33.125,78.875 36.325,78.875
AVEE_MIXER21 on Bottom Layer "AVEE_MIXER21_L04_P017" (solid, pour order 17): 76,71.32 76,68.295 75.725,68.02 75.725,66.47 77.6,66.47 77.6,71.32
AGND on Bottom Layer "AGND_L04_P019" (solid, pour order 19): 71.145,71.395 76,71.395 76,66.47 71.42,66.47 71.42,66.545 71.145,66.545
AGND on Bottom Layer "AGND_L04_P022" (solid, pour order 22): 71.145,85.395 76,85.395 76,80.47 71.42,80.47 71.42,80.545 71.145,80.545
AVEE_MIXER11 on Bottom Layer "AVEE_MIXER11_L04_P020" (solid, pour order 20): 76,85.32 76,82.295 75.725,82.02 75.725,80.47 77.6,80.47 77.6,85.32
AGND on Bottom Layer "AGND_L04_P016" (solid, pour order 16): 71.145,30.375 76,30.375 76,25.45 71.42,25.45 71.42,25.525 71.145,25.525
AVEE_MIXER22 on Bottom Layer "AVEE_MIXER22_L04_P014" (solid, pour order 14): 76,30.3 76,27.275 75.725,27 75.725,25.45 77.6,25.45 77.6,30.3
AGND on Bottom Layer "AGND_L04_P013" (solid, pour order 13): 71.145,16.375 76,16.375 76,11.45 71.42,11.45 71.42,11.525 71.145,11.525
AVDD_MIXER12 on Bottom Layer "AVDD_MIXER12_L04_P012" (solid, pour order 12): 71.145,16.375 71.145,13.35 71.42,13.075 71.42,11.525 69.545,11.525 69.545,16.375
AVEE_MIXER12 on Bottom Layer "AVEE_MIXER12_L04_P011" (solid, pour order 11): 76,16.3 76,13.275 75.725,13 75.725,11.45 77.6,11.45 77.6,16.3
AVEE_AMP12 on Bottom Layer "NONET_L-01_P-001" (solid, pour order 6): 26.55,21.075 22.9,21.075 22.9,17.65 24.85,17.65 24.85,16.05 26.55,16.05
AVDD_AMP12 on Bottom Layer "NONET_L-01_P-001" (solid, pour order 5): 30.425,23.725 32.575,23.725 32.575,24.35 36.675,24.35 36.675,21.2 32.575,21.2 32.575,22.45 30.425,22.45
AVDD_AMP11 on Top Layer "NONET_L-01_P-001" (solid, pour order 27): 30.425,81.347 32.575,81.347 32.575,81.972 36.675,81.972 36.675,80.072 32.575,80.072 30.425,80.072
AVEE_AMP11 on Top Layer "NONET_L-01_P-001" (solid, pour order 26): 26.55,78.697 22.9,78.697 22.9,75.272 24.85,75.272 24.85,73.672 26.55,73.672
AGND on Top Layer "AGND_L01_P025" (solid, pour order 25): 67.3,59.175 67.3,42.15 99.975,42.15 99.975,59.175
NetC29_1 on Top Layer "NETC29_1_L01_P010" (solid, pour order 10): 70.175,57.9 70.175,54.275 76.575,54.275 76.575,57.9
NetC28_1 on Top Layer "NETC28_1_L01_P009" (solid, pour order 9): 79.45,57.825 79.45,52.525 81.175,52.525 81.175,53.175 83.525,53.175 83.525,55.2 84.025,55.2 84.025,57.825
NetC21_2 on Top Layer "NETC21_2_L01_P008" (solid, pour order 8): 71.825,50.65 75.45,50.65 75.45,47.85 76.25,47.85 76.25,47.15 74.75,47.15 74.75,46.6 69,46.6 69,48.25 71.825,48.25
VDD_13P0V on Top Layer "VDD_13P0V_L01_P007" (solid, pour order 7): 79.1,44.425 83.2,44.425 83.2,48.3 81,48.3 81,50.4 79.1,50.4 81,50.4 79.1,50.4
AVEE_AMP12 on Top Layer "NONET_L-01_P-001" (solid, pour order 4): 26.55,21.075 22.9,21.075 22.9,17.65 24.85,17.65 24.85,16.05 26.55,16.05
AVDD_AMP12 on Top Layer "NONET_L-01_P-001" (solid, pour order 3): 30.425,23.725 32.575,23.725 32.575,24.35 36.675,24.35 36.675,22.45 32.575,22.45 30.425,22.45
+AVDD_5P5V on PWR (split plane): 40.174,82.325 40.174,70.75 40.179,70.691 40.196,70.635 40.224,70.583 40.262,70.537 40.308,70.499 40.36,70.471 40.416,70.454 40.475,70.449 51.25,70.449 51.309,70.454 51.365,70.471 51.417,70.499 51.463,70.537 51.501,70.583 51.529,70.635 51.546,70.691 51.551,70.75 51.551,82.024 71.624,82.024 71.624,61.126 66.475,61.126 66.416,61.121 66.36,61.104 66.308,61.076 66.262,61.038 66.224,60.992 66.196,60.94 66.179,60.884 66.174,60.825 66.174,50.425 66.179,50.366 66.196,50.31 66.224,50.258 66.262,50.212 66.308,50.174 66.36,50.146 66.416,50.129 66.475,50.124 71.999,50.124 71.999,9.551 55.626,9.551 55.626,24.4 55.621,24.459 55.604,24.515 55.576,24.567 55.538,24.613 55.492,24.651 55.44,24.679 55.384,24.696 55.325,24.701 33.926,24.701 33.926,84.749 40.174,84.749
+AVEE_5P5V on PWR (split plane): 99.49,0.51 0.51,0.51 0.51,99.49 99.49,99.49
AGND on AGND (split plane): 99.49,0.51 0.51,0.51 0.51,99.49 99.49,99.49

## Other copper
PWR (plane layer: these items are gaps in the copper):
  rectangle: 50.202,17.243 51.302,19.443
  rectangle: 50.202,72.243 51.302,74.443
  lines w0.6: 33.625,24.4 33.625,85.05 40.475,85.05 40.475,82.325 40.475,70.75 51.25,70.75 51.25,82.325 71.925,82.325 71.925,60.825 66.475,60.825 66.475,50.425 72.3,50.425 72.3,9.25 55.325,9.25 55.325,24.4 33.625,24.4

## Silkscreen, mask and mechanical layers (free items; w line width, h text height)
Mechanical 1:
  the board outline again, w0.254
NOTE:
  text "FRONT" at -2.056,31.952 h5 r90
